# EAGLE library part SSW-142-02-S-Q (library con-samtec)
THROUGH-HOLE .025" SQ POST SOCKET Source: Samtec SSW.pdf
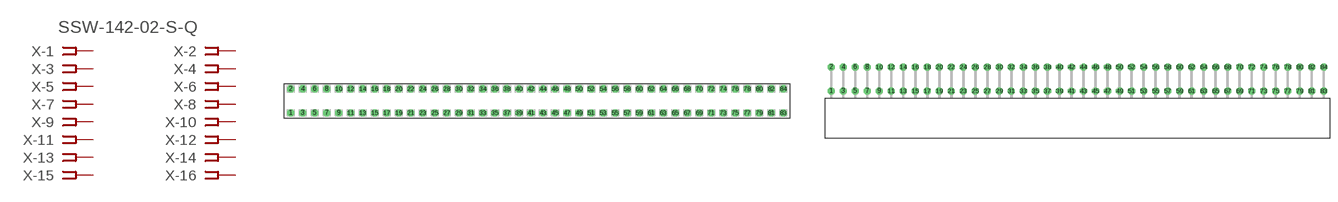
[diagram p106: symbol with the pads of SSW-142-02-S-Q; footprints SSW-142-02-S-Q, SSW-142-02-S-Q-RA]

Designator prefix X; gates -1=FPINV -2=FPIN -3=FPIN -4=FPIN -5=FPIN -6=FPIN -7=FPIN -8=FPIN -9=FPIN -10=FPIN -11=FPIN -12=FPIN -13=FPIN -14=FPIN -15=FPIN -16=FPIN -17=FPIN -18=FPIN -19=FPIN -20=FPIN -21=FPIN -22=FPIN -23=FPIN -24=FPIN -25=FPIN -26=FPIN -27=FPIN -28=FPIN -29=FPIN -30=FPIN -31=FPIN -32=FPIN -33=FPIN -34=FPIN -35=FPIN -36=FPIN -37=FPIN -38=FPIN -39=FPIN -40=FPIN -41=FPIN -42=FPIN -43=FPIN -44=FPIN -45=FPIN -46=FPIN -47=FPIN -48=FPIN -49=FPIN -50=FPIN -51=FPIN -52=FPIN -53=FPIN -54=FPIN -55=FPIN -56=FPIN -57=FPIN -58=FPIN -59=FPIN -60=FPIN -61=FPIN -62=FPIN -63=FPIN -64=FPIN -65=FPIN -66=FPIN -67=FPIN -68=FPIN -69=FPIN -70=FPIN -71=FPIN -72=FPIN -73=FPIN -74=FPIN -75=FPIN -76=FPIN -77=FPIN -78=FPIN -79=FPIN -80=FPIN -81=FPIN -82=FPIN -83=FPIN -84=FPIN

## SSW-142-02-S-Q (OC_FARNELL: unknown; OC_NEWARK: unknown)  [SSW-142-02-S-Q]
1  -1:1  pas
2  -2:1  pas
3  -3:1  pas
4  -4:1  pas
5  -5:1  pas
6  -6:1  pas
7  -7:1  pas
8  -8:1  pas
9  -9:1  pas
10  -10:1  pas
11  -11:1  pas
12  -12:1  pas
13  -13:1  pas
14  -14:1  pas
15  -15:1  pas
16  -16:1  pas
17  -17:1  pas
18  -18:1  pas
19  -19:1  pas
20  -20:1  pas
21  -21:1  pas
22  -22:1  pas
23  -23:1  pas
24  -24:1  pas
25  -25:1  pas
26  -26:1  pas
27  -27:1  pas
28  -28:1  pas
29  -29:1  pas
30  -30:1  pas
31  -31:1  pas
32  -32:1  pas
33  -33:1  pas
34  -34:1  pas
35  -35:1  pas
36  -36:1  pas
37  -37:1  pas
38  -38:1  pas
39  -39:1  pas
40  -40:1  pas
41  -41:1  pas
42  -42:1  pas
43  -43:1  pas
44  -44:1  pas
45  -45:1  pas
46  -46:1  pas
47  -47:1  pas
48  -48:1  pas
49  -49:1  pas
50  -50:1  pas
51  -51:1  pas
52  -52:1  pas
53  -53:1  pas
54  -54:1  pas
55  -55:1  pas
56  -56:1  pas
57  -57:1  pas
58  -58:1  pas
59  -59:1  pas
60  -60:1  pas
61  -61:1  pas
62  -62:1  pas
63  -63:1  pas
64  -64:1  pas
65  -65:1  pas
66  -66:1  pas
67  -67:1  pas
68  -68:1  pas
69  -69:1  pas
70  -70:1  pas
71  -71:1  pas
72  -72:1  pas
73  -73:1  pas
74  -74:1  pas
75  -75:1  pas
76  -76:1  pas
77  -77:1  pas
78  -78:1  pas
79  -79:1  pas
80  -80:1  pas
81  -81:1  pas
82  -82:1  pas
83  -83:1  pas
84  -84:1  pas

## SSW-142-02-S-QRA (OC_FARNELL: unknown; OC_NEWARK: unknown)  [SSW-142-02-S-Q-RA]
Pads as for SSW-142-02-S-Q

## Footprint SSW-142-02-S-Q (pad centres in mm)
THROUGH-HOLE .025" SQ POST SOCKET Source: Samtec SSW.pdf
drill 1 pad 1.5 octagon: 1 -52.07,-2.54; 2 -52.07,2.54; 3 -49.53,-2.54; 4 -49.53,2.54; 5 -46.99,-2.54; 6 -46.99,2.54; 7 -44.45,-2.54; 8 -44.45,2.54; 9 -41.91,-2.54; 10 -41.91,2.54; 11 -39.37,-2.54; 12 -39.37,2.54; 13 -36.83,-2.54; 14 -36.83,2.54; 15 -34.29,-2.54; 16 -34.29,2.54; 17 -31.75,-2.54; 18 -31.75,2.54; 19 -29.21,-2.54; 20 -29.21,2.54; 21 -26.67,-2.54; 22 -26.67,2.54; 23 -24.13,-2.54; 24 -24.13,2.54; 25 -21.59,-2.54; 26 -21.59,2.54; 27 -19.05,-2.54; 28 -19.05,2.54; 29 -16.51,-2.54; 30 -16.51,2.54; 31 -13.97,-2.54; 32 -13.97,2.54; 33 -11.43,-2.54; 34 -11.43,2.54; 35 -8.89,-2.54; 36 -8.89,2.54; 37 -6.35,-2.54; 38 -6.35,2.54; 39 -3.81,-2.54; 40 -3.81,2.54; 41 -1.27,-2.54; 42 -1.27,2.54; 43 1.27,-2.54; 44 1.27,2.54; 45 3.81,-2.54; 46 3.81,2.54; 47 6.35,-2.54; 48 6.35,2.54; 49 8.89,-2.54; 50 8.89,2.54; 51 11.43,-2.54; 52 11.43,2.54; 53 13.97,-2.54; 54 13.97,2.54; 55 16.51,-2.54; 56 16.51,2.54; 57 19.05,-2.54; 58 19.05,2.54; 59 21.59,-2.54; 60 21.59,2.54; 61 24.13,-2.54; 62 24.13,2.54; 63 26.67,-2.54; 64 26.67,2.54; 65 29.21,-2.54; 66 29.21,2.54; 67 31.75,-2.54; 68 31.75,2.54; 69 34.29,-2.54; 70 34.29,2.54; 71 36.83,-2.54; 72 36.83,2.54; 73 39.37,-2.54; 74 39.37,2.54; 75 41.91,-2.54; 76 41.91,2.54; 77 44.45,-2.54; 78 44.45,2.54; 79 46.99,-2.54; 80 46.99,2.54; 81 49.53,-2.54; 82 49.53,2.54; 83 52.07,-2.54; 84 52.07,2.54

## Footprint SSW-142-02-S-Q-RA (pad centres in mm)
THROUGH-HOLE .025" SQ POST SOCKET Source: Samtec SSW.pdf
drill 1 pad 1.5 octagon: 1 -52.07,1.524; 2 -52.07,6.604; 3 -49.53,1.524; 4 -49.53,6.604; 5 -46.99,1.524; 6 -46.99,6.604; 7 -44.45,1.524; 8 -44.45,6.604; 9 -41.91,1.524; 10 -41.91,6.604; 11 -39.37,1.524; 12 -39.37,6.604; 13 -36.83,1.524; 14 -36.83,6.604; 15 -34.29,1.524; 16 -34.29,6.604; 17 -31.75,1.524; 18 -31.75,6.604; 19 -29.21,1.524; 20 -29.21,6.604; 21 -26.67,1.524; 22 -26.67,6.604; 23 -24.13,1.524; 24 -24.13,6.604; 25 -21.59,1.524; 26 -21.59,6.604; 27 -19.05,1.524; 28 -19.05,6.604; 29 -16.51,1.524; 30 -16.51,6.604; 31 -13.97,1.524; 32 -13.97,6.604; 33 -11.43,1.524; 34 -11.43,6.604; 35 -8.89,1.524; 36 -8.89,6.604; 37 -6.35,1.524; 38 -6.35,6.604; 39 -3.81,1.524; 40 -3.81,6.604; 41 -1.27,1.524; 42 -1.27,6.604; 43 1.27,1.524; 44 1.27,6.604; 45 3.81,1.524; 46 3.81,6.604; 47 6.35,1.524; 48 6.35,6.604; 49 8.89,1.524; 50 8.89,6.604; 51 11.43,1.524; 52 11.43,6.604; 53 13.97,1.524; 54 13.97,6.604; 55 16.51,1.524; 56 16.51,6.604; 57 19.05,1.524; 58 19.05,6.604; 59 21.59,1.524; 60 21.59,6.604; 61 24.13,1.524; 62 24.13,6.604; 63 26.67,1.524; 64 26.67,6.604; 65 29.21,1.524; 66 29.21,6.604; 67 31.75,1.524; 68 31.75,6.604; 69 34.29,1.524; 70 34.29,6.604; 71 36.83,1.524; 72 36.83,6.604; 73 39.37,1.524; 74 39.37,6.604; 75 41.91,1.524; 76 41.91,6.604; 77 44.45,1.524; 78 44.45,6.604; 79 46.99,1.524; 80 46.99,6.604; 81 49.53,1.524; 82 49.53,6.604; 83 52.07,1.524; 84 52.07,6.604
